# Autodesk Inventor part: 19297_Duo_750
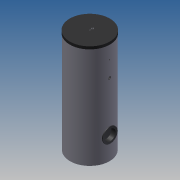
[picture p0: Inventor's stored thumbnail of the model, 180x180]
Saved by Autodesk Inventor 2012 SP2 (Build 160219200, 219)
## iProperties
allow_slope_adjustment: 0 ul
connection_type: 13 ul
flow_configuration2: 1 ul
flow_direction: 2 ul
loss_method: 0 ul
radius: 12,250 mm
radius: 22,625 mm
radius: 19,625 mm
description: 0:0:19298_Duo_750
manufacturer: 0:0:Flamco Group
model: 0:0:Duo 750
url: 0:0:www.flamcogroup.com
radius: 9,500 mm
Created: 2014-05
Part Number: 19297_Duo_750
Material: Default
Document SubType Name: Modeling
Designer: michel
Density: 1 g/cm^3
radius: 18,295 mm
Author: michel
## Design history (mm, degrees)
sketch "Sketch1"
  geometry: C1 r 375 at (0, 0); 1 further point
  constraints: 1 centre point, 1 coincident
  dimensions: "d0" = 750 diameter of C1
extrude "Extrusion1" new body sketch "Sketch1" distance "d1" = 1970; taper "d2" = 0 deg
sketch "Sketch2"
  geometry: L1 (-375, 1970)-(375, 1970) reference; L2 (-375, 0)-(375, 0) reference; L3 (375, 0)-(375, 1970) reference; L4 (375, 1970)-(380, 1970); L5 (380, 1970)-(380, 1920); L6 (380, 1920)-(375, 1920); L7 (375, 1920)-(375, 1970); L8 (0, -366)-(0, 2196) reference; 1 further point
  constraints: 8 end point, 2 parallel, 1 horizontal, 1 perpendicular
  dimensions: "d3" = 5 distance of L5.end L6.end; "d4" = 50 distance of L4.end L5.end
revolve "Revolution1" sketch "Sketch2" stored, may be unused: angle "d5" = 90 deg
workplane "Work Plane1"
workplane "Work Plane2"
workplane "Work Plane3"
workplane "Work Plane4"
workplane "Work Plane5"
workplane "Work Plane6"
workplane "Work Plane11"
workplane "Work Plane12"
sketch "Sketch3"
  geometry: L1 (526.398, 1880)-(-525.233, 1880) reference; L2 (526.398, 1040)-(-525.233, 1040) reference; L3 (526.398, 890)-(-525.233, 890) reference; L4 (526.398, 320)-(-525.233, 320) reference; L5 (526.398, 60)-(-525.233, 60) reference; L6 (375, 0)-(375, 1920) reference; L7 (375, 1880)-(335, 1880); L8 (335, 1880)-(335, 1900.955); L9 (335, 1900.955)-(375, 1900.955); L10 (375, 1900.955)-(375, 1880); L11 (375, 1040)-(335, 1040); L12 (335, 1040)-(335, 1060.955); L13 (335, 1060.955)-(375, 1060.955); L14 (375, 1060.955)-(375, 1040); L15 (335, 1861.705)-(335, 1859.045); L16 (335, 1859.045)-(376, 1859.045); L17 (376, 1859.045)-(376, 1861.705); L18 (376, 1861.705)-(335, 1861.705); L19 (335, 890)-(335, 903.22); L20 (375, 890)-(335, 890); L21 (335, 903.22)-(375, 903.22); L22 (375, 903.22)-(375, 890); L23 (335, 877.75)-(335, 876.78); L24 (335, 876.78)-(376, 876.78); L25 (376, 876.78)-(376, 877.75); L26 (376, 877.75)-(335, 877.75); L27 (335.165, 340.955)-(375.165, 340.955); L28 (335.165, 320)-(335.165, 340.955); L29 (375.165, 320)-(335.165, 320); L30 (375.165, 340.955)-(375.165, 320); L31 (376.165, 300.375)-(335.165, 300.375); L32 (335.165, 300.375)-(335.165, 299.045); L33 (335.165, 299.045)-(376.165, 299.045); L34 (376.165, 299.045)-(376.165, 300.375); L35 (335, 80.955)-(375, 80.955); L36 (335, 60)-(335, 80.955); L37 (375, 60)-(335, 60); L38 (375, 80.955)-(375, 60); L39 (376, 40.375)-(335, 40.375); L40 (335, 40.375)-(335, 39.045); L41 (335, 39.045)-(376, 39.045); L42 (376, 39.045)-(376, 40.375); L43 (335, 1019.045)-(375, 1019.045); L44 (335, 1020.375)-(335, 1019.045); L45 (375, 1019.045)-(376, 1019.045); L46 (376, 1019.045)-(376, 1020.375); L47 (376, 1020.375)-(335, 1020.375); L48 (-541, 1670)-(533.5, 1670) reference; L49 (-541, 1370)-(533.5, 1370) reference; L50 (-375, 0)-(-375, 1920) reference; L51 (-375, 1670)-(-335, 1670); L52 (-335, 1670)-(-335, 1680.475); L53 (-335, 1680.475)-(-375, 1680.475); L54 (-375, 1680.475)-(-375, 1670); L55 (-376, 1659.525)-(-335, 1659.525); L56 (-335, 1659.525)-(-335, 1660.5); L57 (-335, 1660.5)-(-376, 1660.5); L58 (-376, 1660.5)-(-376, 1659.525); L59 (-375, 1370)-(-335, 1370); L60 (-335, 1370)-(-335, 1393.9); L61 (-335, 1393.9)-(-375, 1393.9); L62 (-375, 1393.9)-(-375, 1370); L63 (-376, 1346.1)-(-335, 1346.1); L64 (-335, 1346.1)-(-335, 1347.375)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; 2 further points
  constraints: 114 end point, 17 parallel, 8 horizontal, 7 perpendicular, 6 point on line
  dimensions: "d19" = 40 distance of L8.end L9.end; "d21" = 40 distance of L12.end L13.end; "d70" = 20.955 distance between parallel lines of L1 L9; "d73" = 40 distance of L19.end L21.end; "d74" = 40 distance of L27.start L27.end; "d75" = 40 distance of L35.start L35.end; "d76" = 13.22 distance between parallel lines of L3 L21; "d85" = 20.955 distance between parallel lines of L2 L13; "d108" = 20.955 distance between parallel lines of L1 L16 (= d70); "d109" = 2.66 distance between parallel lines of L18 L16 (computed from d70); "d110" = 20.955 distance between parallel lines of L11 L13 (= d85); "d111" = 20.955 distance between parallel lines of L2 L43 (= d85); "d112" = 1.33 distance between parallel lines of L47 L43 (computed from d85); "d113" = 13.22 distance between parallel lines of L20 L21 (= d76); "d114" = 13.22 distance between parallel lines of L24 L3 (= d76); "d115" = 0.97 distance between parallel lines of L26 L24 (computed from d76); "d116" = 20.955 distance between parallel lines of L4 L27; "d117" = 20.955 distance of L27.start L28.start (= d116); "d118" = 20.955 distance between parallel lines of L33 L4 (= d116); "d119" = 1.33 distance between parallel lines of L31 L33 (computed from d116); "d120" = 20.955 distance from line of L35 L36.start (= d121); "d121" = 20.955 distance between parallel lines of L5 L35; "d122" = 20.955 distance between parallel lines of L41 L5 (= d121); "d123" = 1.33 distance between parallel lines of L39 L41 (computed from d121); "d129" = 40 distance of L53.end L52.end; "d130" = 10.475 distance of L52.end L51.end; "d131" = 10.475 distance between parallel lines of L48 L55; "d132" = 0.975 distance between parallel lines of L57 L55; "d134" = 23.9 distance between parallel lines of L49 L61; "d135" = 23.9 distance between parallel lines of L49 L63; "d136" = 1.275 distance between parallel lines of L65 L63
revolve "Revolution2" stored, may be unused: angle "d23" = 90 deg
sketch "Sketch5"
  geometry: L1 (-375, 0)-(-375, 1920) reference; L2 (-375, 0)-(-375, 435); L3 (-220, 435)-(-594, 435); L4 (-375, 435)-(-387.5, 435); L5 (-387.5, 435)-(-387.5, 575); L6 (-387.5, 575)-(-375, 575); L7 (-375, 575)-(-375, 435); L8 (-375, 0)-(375, 0) reference; 1 further point
  constraints: 12 end point, 2 parallel, 2 perpendicular, 1 horizontal, 1 point on line
  dimensions: "d35" = 435 distance of L1.start L2.end; "d36" = 12.5 distance of L5.end L6.end; "d37" = 140 distance of L4.end L5.end; "d124" = 435 distance between parallel lines of L8 L3 (= d35)
revolve "Revolution7" sketch "Sketch5" stored, may be unused: angle "d38" = 90 deg
sketch "Sketch6"
  geometry: C1 r 122.5 at (0, 0); A1 r 140 centre (0, 0) between (140, 0) and (-140, 0) reference; 1 further point
  constraints: 1 centre point, 1 coincident
  dimensions: "d39" = 245 diameter of C1
extrude "Extrusion3" join sketch "Sketch6" stored distance "d40" = 40; taper "d41" = 0 deg
sketch "Sketch7"
  geometry: C1 r 140 at (0, 0) reference; C2 r 102.5 at (0, 0); 1 further point
  constraints: 1 centre point, 1 coincident
  dimensions: "d42" = 205 diameter of C2
extrude "Extrusion4" cut sketch "Sketch7" distance "d43" = 80; taper "d44" = 0 deg
sketch "Sketch15"
  geometry: L1 (-533.5, 0)-(541, 0) reference; C1 r 20.955 at (0, 50); C2 r 380 at (0, 0) reference; C3 r 10.475 at (0, 0); C4 r 19.625 at (0, 50); C5 r 9.5 at (0, 0)
  constraints: 4 centre point, 3 coincident
  dimensions: "d142" = 41.91 diameter of C1; "d143" = 50 distance from line of L1 C1.centre; "d144" = 20.95 diameter of C3; "d145" = 39.25 diameter of C4; "d146" = 19 diameter of C5
revolve "Revolution9" stored, may be unused: angle "d69" = 90 deg
revolve "Revolution10" stored, may be unused: angle "d92" = 90 deg
revolve "Revolution11" stored, may be unused: angle "d93" = 90 deg
revolve "Revolution12" stored, may be unused: angle "d94" = 90 deg
revolve "Revolution13" stored, may be unused: angle "d95" = 90 deg
revolve "Revolution14" stored, may be unused: angle "d96" = 90 deg
revolve "Revolution15" stored, may be unused: angle "d97" = 90 deg
revolve "Revolution16" stored, may be unused: angle "d98" = 90 deg
revolve "Revolution17" stored, may be unused: angle "d99" = 90 deg
revolve "Revolution18" stored, may be unused: angle "d138" = 90 deg
revolve "Revolution19" stored, may be unused: angle "d139" = 90 deg
revolve "Revolution20" stored, may be unused: angle "d140" = 90 deg
revolve "Revolution21" stored, may be unused: angle "d141" = 90 deg
extrude "Extrusion11" cut sketch "Sketch15" distance "d147" = 40; taper "d148" = 0 deg
extrude "Extrusion12" join sketch "Sketch15" distance "d149" = 2; taper "d150" = 0 deg
body "Solid1"
node "Projected Loop1"
other parameters: "d12" = 0
